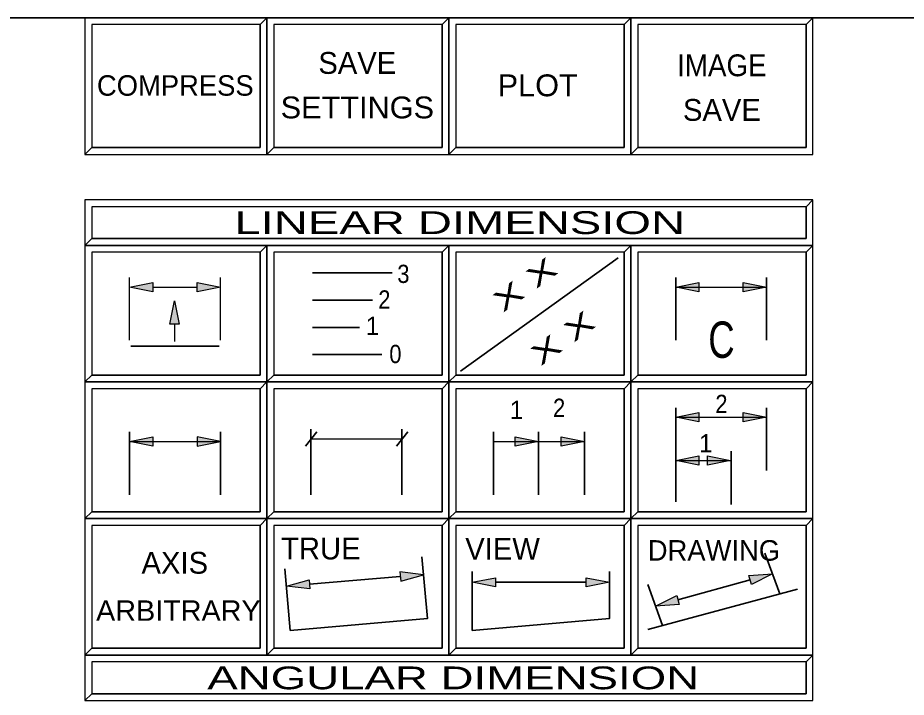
# Model space of a CAD drawing. Extents: x 95906.8 to 95923.6, y 90964.8 to 90972.8.
# Drawn here: x 95908.785 to 95910.737, y 90971.269 to 90972.762 of the extents above; entities that cross this region are included whole.
import ezdxf
from ezdxf.enums import TextEntityAlignment as Align

# ---------------------------------------------------------------- set-up
doc = ezdxf.new("R2010")
doc.units = 0
doc.header["$LTSCALE"] = 0.019
for name, color, linetype, lineweight in [('1', 7, 'Continuous', 25), ('11', 7, 'Continuous', 25), ('12', 7, 'Continuous', 25), ('17', 7, 'Continuous', 25), ('2', 7, 'Continuous', 13), ('3', 7, 'Continuous', 25), ('6', 7, 'Continuous', 35), ('7', 7, 'Continuous', 35)]:
    doc.layers.add(name, color=color, linetype=linetype, lineweight=lineweight)

msp = doc.modelspace()

# ---------------------------------------------------------------- hatches: boundary and pattern name
at = {"layer": '6'}
for points in [[(95909.0307, 90972.1701), (95909.0819, 90972.1803), (95909.0819, 90972.1599)], [(95909.1793, 90972.1803), (95909.2305, 90972.1701), (95909.1793, 90972.1599)], [(95910.2307, 90972.1701), (95910.2819, 90972.1803), (95910.2819, 90972.1599)], [(95910.3793, 90972.1803), (95910.4305, 90972.1701), (95910.3793, 90972.1599)], [(95909.1291, 90972.1397), (95909.1393, 90972.0885), (95909.1189, 90972.0885)], [(95910.2307, 90971.8841), (95910.2819, 90971.8943), (95910.2819, 90971.8739)], [(95910.3793, 90971.8943), (95910.4305, 90971.8841), (95910.3793, 90971.8739)], [(95909.0307, 90971.8308), (95909.0819, 90971.841), (95909.0819, 90971.8206)], [(95909.2305, 90971.8308), (95909.1793, 90971.841), (95909.1793, 90971.8206)], [(95909.8778, 90971.841), (95909.929, 90971.8308), (95909.8778, 90971.8206)], [(95909.9793, 90971.841), (95910.0305, 90971.8308), (95909.9793, 90971.8206)], [(95910.2307, 90971.7889), (95910.2819, 90971.7991), (95910.2819, 90971.7787)], [(95910.3003, 90971.7991), (95910.3515, 90971.7889), (95910.3003, 90971.7787)], [(95909.6767, 90971.5384), (95909.6248, 90971.5443), (95909.6265, 90971.5239)], [(95909.7835, 90971.5216), (95909.8347, 90971.5318), (95909.8347, 90971.5114)], [(95910.0339, 90971.5318), (95910.0851, 90971.5216), (95910.0339, 90971.5114)], [(95910.3915, 90971.5366), (95910.4436, 90971.5403), (95910.397, 90971.5168)], [(95909.3751, 90971.5129), (95909.4253, 90971.5274), (95909.427, 90971.507)], [(95910.1865, 90971.4695), (95910.2331, 90971.493), (95910.2386, 90971.4732)]]:
    msp.add_hatch(color=256, dxfattribs=at).paths.add_polyline_path(points)

# ---------------------------------------------------------------- linework, layer by layer
at = {"layer": '1'}
for points in [[(95908.9323, 90972.4617), (95909.3323, 90972.4617), (95909.3323, 90972.7617), (95908.9323, 90972.7617)], [(95909.3323, 90972.4617), (95909.7323, 90972.4617), (95909.7323, 90972.7617), (95909.3323, 90972.7617)], [(95909.7323, 90972.4617), (95910.1323, 90972.4617), (95910.1323, 90972.7617), (95909.7323, 90972.7617)], [(95910.1323, 90972.4617), (95910.5323, 90972.4617), (95910.5323, 90972.7617), (95910.1323, 90972.7617)], [(95908.9323, 90972.2617), (95910.5323, 90972.2617), (95910.5323, 90972.3617), (95908.9323, 90972.3617)], [(95908.9323, 90971.9617), (95909.3323, 90971.9617), (95909.3323, 90972.2617), (95908.9323, 90972.2617)], [(95909.3323, 90971.9617), (95909.7323, 90971.9617), (95909.7323, 90972.2617), (95909.3323, 90972.2617)], [(95909.7323, 90971.9617), (95910.1323, 90971.9617), (95910.1323, 90972.2617), (95909.7323, 90972.2617)], [(95910.1323, 90971.9617), (95910.5323, 90971.9617), (95910.5323, 90972.2617), (95910.1323, 90972.2617)], [(95908.9323, 90971.6617), (95909.3323, 90971.6617), (95909.3323, 90971.9617), (95908.9323, 90971.9617)], [(95909.3323, 90971.6617), (95909.7323, 90971.6617), (95909.7323, 90971.9617), (95909.3323, 90971.9617)], [(95909.7323, 90971.6617), (95910.1323, 90971.6617), (95910.1323, 90971.9617), (95909.7323, 90971.9617)], [(95910.1323, 90971.6617), (95910.5323, 90971.6617), (95910.5323, 90971.9617), (95910.1323, 90971.9617)], [(95908.9323, 90971.3617), (95909.3323, 90971.3617), (95909.3323, 90971.6617), (95908.9323, 90971.6617)], [(95909.3323, 90971.3617), (95909.7323, 90971.3617), (95909.7323, 90971.6617), (95909.3323, 90971.6617)], [(95909.7323, 90971.3617), (95910.1323, 90971.3617), (95910.1323, 90971.6617), (95909.7323, 90971.6617)], [(95910.1323, 90971.3617), (95910.5323, 90971.3617), (95910.5323, 90971.6617), (95910.1323, 90971.6617)], [(95908.9323, 90971.2617), (95910.5323, 90971.2617), (95910.5323, 90971.3617), (95908.9323, 90971.3617)]]:
    msp.add_lwpolyline(points, close=True, dxfattribs=at)
at = {"layer": '11'}
for points in [[(95908.9473, 90972.4767), (95909.3173, 90972.4767), (95909.3173, 90972.7467), (95908.9473, 90972.7467)], [(95909.3473, 90972.4767), (95909.7173, 90972.4767), (95909.7173, 90972.7467), (95909.3473, 90972.7467)], [(95909.7473, 90972.4767), (95910.1173, 90972.4767), (95910.1173, 90972.7467), (95909.7473, 90972.7467)], [(95908.9473, 90971.9767), (95909.3173, 90971.9767), (95909.3173, 90972.2467), (95908.9473, 90972.2467)], [(95909.3473, 90971.9767), (95909.7173, 90971.9767), (95909.7173, 90972.2467), (95909.3473, 90972.2467)], [(95909.7473, 90971.9767), (95910.1173, 90971.9767), (95910.1173, 90972.2467), (95909.7473, 90972.2467)], [(95910.1473, 90971.9767), (95910.5173, 90971.9767), (95910.5173, 90972.2467), (95910.1473, 90972.2467)], [(95909.3473, 90971.6767), (95909.7173, 90971.6767), (95909.7173, 90971.9467), (95909.3473, 90971.9467)], [(95909.7473, 90971.6767), (95910.1173, 90971.6767), (95910.1173, 90971.9467), (95909.7473, 90971.9467)], [(95910.1473, 90971.6767), (95910.5173, 90971.6767), (95910.5173, 90971.9467), (95910.1473, 90971.9467)], [(95908.9473, 90971.3767), (95909.3173, 90971.3767), (95909.3173, 90971.6467), (95908.9473, 90971.6467)], [(95909.3473, 90971.3767), (95909.7173, 90971.3767), (95909.7173, 90971.6467), (95909.3473, 90971.6467)], [(95909.7473, 90971.3767), (95910.1173, 90971.3767), (95910.1173, 90971.6467), (95909.7473, 90971.6467)], [(95910.1473, 90971.3767), (95910.5173, 90971.3767), (95910.5173, 90971.6467), (95910.1473, 90971.6467)]]:
    msp.add_lwpolyline(points, close=True, dxfattribs=at)
at = {"layer": '12'}
for points in [[(95910.1473, 90972.4767), (95910.5173, 90972.4767), (95910.5173, 90972.7467), (95910.1473, 90972.7467)], [(95908.9473, 90971.6767), (95909.3173, 90971.6767), (95909.3173, 90971.9467), (95908.9473, 90971.9467)]]:
    msp.add_lwpolyline(points, close=True, dxfattribs=at)
at = {"layer": '17'}
for points in [[(95908.9473, 90972.2767), (95910.5173, 90972.2767), (95910.5173, 90972.3467), (95908.9473, 90972.3467)], [(95908.9473, 90971.2767), (95910.5173, 90971.2767), (95910.5173, 90971.3467), (95908.9473, 90971.3467)]]:
    msp.add_lwpolyline(points, close=True, dxfattribs=at)
at = {"layer": '2'}
for points in [[(95908.9323, 90972.7617), (95908.9323, 90972.4617), (95908.9473, 90972.4767), (95908.9473, 90972.7467), (95909.3173, 90972.7467), (95909.3323, 90972.7617)], [(95909.3323, 90972.7617), (95909.3323, 90972.4617), (95909.3473, 90972.4767), (95909.3473, 90972.7467), (95909.7173, 90972.7467), (95909.7323, 90972.7617)], [(95909.7323, 90972.7617), (95909.7323, 90972.4617), (95909.7473, 90972.4767), (95909.7473, 90972.7467), (95910.1173, 90972.7467), (95910.1323, 90972.7617)], [(95910.1323, 90972.7617), (95910.1323, 90972.4617), (95910.1473, 90972.4767), (95910.1473, 90972.7467), (95910.5173, 90972.7467), (95910.5323, 90972.7617)], [(95908.9323, 90972.3617), (95908.9323, 90972.2617), (95908.9473, 90972.2767), (95908.9473, 90972.3467), (95910.5173, 90972.3467), (95910.5323, 90972.3617)], [(95908.9323, 90972.2617), (95908.9323, 90971.9617), (95908.9473, 90971.9767), (95908.9473, 90972.2467), (95909.3173, 90972.2467), (95909.3323, 90972.2617)], [(95909.3323, 90972.2617), (95909.3323, 90971.9617), (95909.3473, 90971.9767), (95909.3473, 90972.2467), (95909.7173, 90972.2467), (95909.7323, 90972.2617)], [(95909.7323, 90972.2617), (95909.7323, 90971.9617), (95909.7473, 90971.9767), (95909.7473, 90972.2467), (95910.1173, 90972.2467), (95910.1323, 90972.2617)], [(95910.1323, 90972.2617), (95910.1323, 90971.9617), (95910.1473, 90971.9767), (95910.1473, 90972.2467), (95910.5173, 90972.2467), (95910.5323, 90972.2617)], [(95908.9323, 90971.9617), (95908.9323, 90971.6617), (95908.9473, 90971.6767), (95908.9473, 90971.9467), (95909.3173, 90971.9467), (95909.3323, 90971.9617)], [(95909.3323, 90971.9617), (95909.3323, 90971.6617), (95909.3473, 90971.6767), (95909.3473, 90971.9467), (95909.7173, 90971.9467), (95909.7323, 90971.9617)], [(95909.7323, 90971.9617), (95909.7323, 90971.6617), (95909.7473, 90971.6767), (95909.7473, 90971.9467), (95910.1173, 90971.9467), (95910.1323, 90971.9617)], [(95910.1323, 90971.9617), (95910.1323, 90971.6617), (95910.1473, 90971.6767), (95910.1473, 90971.9467), (95910.5173, 90971.9467), (95910.5323, 90971.9617)], [(95908.9323, 90971.6617), (95908.9323, 90971.3617), (95908.9473, 90971.3767), (95908.9473, 90971.6467), (95909.3173, 90971.6467), (95909.3323, 90971.6617)], [(95909.3323, 90971.6617), (95909.3323, 90971.3617), (95909.3473, 90971.3767), (95909.3473, 90971.6467), (95909.7173, 90971.6467), (95909.7323, 90971.6617)], [(95909.7323, 90971.6617), (95909.7323, 90971.3617), (95909.7473, 90971.3767), (95909.7473, 90971.6467), (95910.1173, 90971.6467), (95910.1323, 90971.6617)], [(95910.1323, 90971.6617), (95910.1323, 90971.3617), (95910.1473, 90971.3767), (95910.1473, 90971.6467), (95910.5173, 90971.6467), (95910.5323, 90971.6617)], [(95908.9323, 90971.3617), (95908.9323, 90971.2617), (95908.9473, 90971.2767), (95908.9473, 90971.3467), (95910.5173, 90971.3467), (95910.5323, 90971.3617)]]:
    msp.add_lwpolyline(points, close=True, dxfattribs=at)
at = {"layer": '3'}
for points in [[(95908.9323, 90972.4617), (95909.3323, 90972.4617), (95909.3323, 90972.7617), (95909.3173, 90972.7467), (95909.3173, 90972.4767), (95908.9473, 90972.4767)], [(95909.3323, 90972.4617), (95909.7323, 90972.4617), (95909.7323, 90972.7617), (95909.7173, 90972.7467), (95909.7173, 90972.4767), (95909.3473, 90972.4767)], [(95909.7323, 90972.4617), (95910.1323, 90972.4617), (95910.1323, 90972.7617), (95910.1173, 90972.7467), (95910.1173, 90972.4767), (95909.7473, 90972.4767)], [(95910.1323, 90972.4617), (95910.5323, 90972.4617), (95910.5323, 90972.7617), (95910.5173, 90972.7467), (95910.5173, 90972.4767), (95910.1473, 90972.4767)], [(95908.9323, 90972.2617), (95910.5323, 90972.2617), (95910.5323, 90972.3617), (95910.5173, 90972.3467), (95910.5173, 90972.2767), (95908.9473, 90972.2767)], [(95908.9323, 90971.9617), (95909.3323, 90971.9617), (95909.3323, 90972.2617), (95909.3173, 90972.2467), (95909.3173, 90971.9767), (95908.9473, 90971.9767)], [(95909.3323, 90971.9617), (95909.7323, 90971.9617), (95909.7323, 90972.2617), (95909.7173, 90972.2467), (95909.7173, 90971.9767), (95909.3473, 90971.9767)], [(95909.7323, 90971.9617), (95910.1323, 90971.9617), (95910.1323, 90972.2617), (95910.1173, 90972.2467), (95910.1173, 90971.9767), (95909.7473, 90971.9767)], [(95910.1323, 90971.9617), (95910.5323, 90971.9617), (95910.5323, 90972.2617), (95910.5173, 90972.2467), (95910.5173, 90971.9767), (95910.1473, 90971.9767)], [(95908.9323, 90971.6617), (95909.3323, 90971.6617), (95909.3323, 90971.9617), (95909.3173, 90971.9467), (95909.3173, 90971.6767), (95908.9473, 90971.6767)], [(95909.3323, 90971.6617), (95909.7323, 90971.6617), (95909.7323, 90971.9617), (95909.7173, 90971.9467), (95909.7173, 90971.6767), (95909.3473, 90971.6767)], [(95909.7323, 90971.6617), (95910.1323, 90971.6617), (95910.1323, 90971.9617), (95910.1173, 90971.9467), (95910.1173, 90971.6767), (95909.7473, 90971.6767)], [(95910.1323, 90971.6617), (95910.5323, 90971.6617), (95910.5323, 90971.9617), (95910.5173, 90971.9467), (95910.5173, 90971.6767), (95910.1473, 90971.6767)], [(95908.9323, 90971.3617), (95909.3323, 90971.3617), (95909.3323, 90971.6617), (95909.3173, 90971.6467), (95909.3173, 90971.3767), (95908.9473, 90971.3767)], [(95909.3323, 90971.3617), (95909.7323, 90971.3617), (95909.7323, 90971.6617), (95909.7173, 90971.6467), (95909.7173, 90971.3767), (95909.3473, 90971.3767)], [(95909.7323, 90971.3617), (95910.1323, 90971.3617), (95910.1323, 90971.6617), (95910.1173, 90971.6467), (95910.1173, 90971.3767), (95909.7473, 90971.3767)], [(95910.1323, 90971.3617), (95910.5323, 90971.3617), (95910.5323, 90971.6617), (95910.5173, 90971.6467), (95910.5173, 90971.3767), (95910.1473, 90971.3767)], [(95908.9323, 90971.2617), (95910.5323, 90971.2617), (95910.5323, 90971.3617), (95910.5173, 90971.3467), (95910.5173, 90971.2767), (95908.9473, 90971.2767)]]:
    msp.add_lwpolyline(points, close=True, dxfattribs=at)
at = {"layer": '6'}
for p, q in [((95909.7575, 90971.9856), (95910.1045, 90972.2341)), ((95909.4323, 90972.2017), (95909.6076, 90972.2017)), ((95910.2307, 90972.0533), (95910.2307, 90972.1912)), ((95910.4305, 90972.0533), (95910.4305, 90972.1912)), ((95909.4323, 90972.1417), (95909.5646, 90972.1417)), ((95909.4323, 90972.0817), (95909.5356, 90972.0817)), ((95909.0334, 90972.0407), (95909.2276, 90972.0407)), ((95909.4323, 90972.0217), (95909.5847, 90972.0217)), ((95910.2307, 90971.6987), (95910.2307, 90971.9052)), ((95910.4305, 90971.7673), (95910.4305, 90971.9052)), ((95909.0307, 90971.714), (95909.0307, 90971.8519)), ((95909.2305, 90971.714), (95909.2305, 90971.8519)), ((95909.417, 90971.821), (95909.4423, 90971.8518)), ((95909.4289, 90971.714), (95909.4289, 90971.858)), ((95909.6169, 90971.821), (95909.6422, 90971.8518)), ((95909.6287, 90971.714), (95909.6287, 90971.858)), ((95909.8307, 90971.714), (95909.8307, 90971.8519)), ((95909.929, 90971.714), (95909.929, 90971.8519)), ((95910.0305, 90971.714), (95910.0305, 90971.8519)), ((95910.3526, 90971.6929), (95910.3526, 90971.81)), ((95910.4596, 90971.4961), (95910.427, 90971.5856)), ((95909.3835, 90971.4155), (95909.3716, 90971.5512)), ((95909.4261, 90971.5172), (95909.6256, 90971.5341)), ((95909.7835, 90971.4155), (95909.7835, 90971.5454)), ((95909.8347, 90971.5216), (95910.0339, 90971.5216)), ((95910.2019, 90971.427), (95910.1693, 90971.5165)), ((95910.2358, 90971.4831), (95910.3943, 90971.5267)), ((95910.1695, 90971.4183), (95910.4981, 90971.5064))]:
    msp.add_line(p, q, dxfattribs=at)
at = {"layer": '6', "lineweight": 25}
for p, q in [((95909.0307, 90972.0533), (95909.0307, 90972.1912)), ((95909.2305, 90972.0533), (95909.2305, 90972.1912)), ((95909.0819, 90972.1701), (95909.1793, 90972.1701)), ((95910.2307, 90972.1701), (95910.4305, 90972.1701)), ((95909.1291, 90972.0885), (95909.1291, 90972.0503)), ((95910.2307, 90971.8841), (95910.4305, 90971.8841)), ((95909.0307, 90971.8308), (95909.2305, 90971.8308)), ((95909.4289, 90971.8369), (95909.6287, 90971.8369)), ((95909.8307, 90971.8308), (95910.0305, 90971.8308)), ((95910.2307, 90971.7889), (95910.3515, 90971.7889))]:
    msp.add_line(p, q, dxfattribs=at)
for points in [[(95909.0307, 90972.1701), (95909.0819, 90972.1803), (95909.0819, 90972.1599)], [(95909.1793, 90972.1803), (95909.2305, 90972.1701), (95909.1793, 90972.1599)], [(95910.2307, 90972.1701), (95910.2819, 90972.1803), (95910.2819, 90972.1599)], [(95910.3793, 90972.1803), (95910.4305, 90972.1701), (95910.3793, 90972.1599)], [(95909.1291, 90972.1397), (95909.1393, 90972.0885), (95909.1189, 90972.0885)], [(95910.2307, 90971.8841), (95910.2819, 90971.8943), (95910.2819, 90971.8739)], [(95910.3793, 90971.8943), (95910.4305, 90971.8841), (95910.3793, 90971.8739)], [(95909.0307, 90971.8308), (95909.0819, 90971.841), (95909.0819, 90971.8206)], [(95909.2305, 90971.8308), (95909.1793, 90971.841), (95909.1793, 90971.8206)], [(95909.8778, 90971.841), (95909.929, 90971.8308), (95909.8778, 90971.8206)], [(95909.9793, 90971.841), (95910.0305, 90971.8308), (95909.9793, 90971.8206)], [(95910.2307, 90971.7889), (95910.2819, 90971.7991), (95910.2819, 90971.7787)], [(95910.3003, 90971.7991), (95910.3515, 90971.7889), (95910.3003, 90971.7787)], [(95909.6767, 90971.5384), (95909.6248, 90971.5443), (95909.6265, 90971.5239)], [(95909.7835, 90971.5216), (95909.8347, 90971.5318), (95909.8347, 90971.5114)], [(95910.0339, 90971.5318), (95910.0851, 90971.5216), (95910.0339, 90971.5114)], [(95910.3915, 90971.5366), (95910.4436, 90971.5403), (95910.397, 90971.5168)], [(95909.3751, 90971.5129), (95909.4253, 90971.5274), (95909.427, 90971.507)], [(95910.1865, 90971.4695), (95910.2331, 90971.493), (95910.2386, 90971.4732)]]:
    msp.add_lwpolyline(points, close=True, dxfattribs=at)
at = {"layer": '6'}
for points in [[(95909.3835, 90971.4155), (95909.6851, 90971.4419), (95909.6732, 90971.5776)], [(95909.7835, 90971.4155), (95910.0851, 90971.4419), (95910.0851, 90971.5454)]]:
    msp.add_lwpolyline(points, dxfattribs=at)
at = {"layer": '7'}
msp.add_lwpolyline([(95906.8323, 90972.7617), (95918.8323, 90972.7617), (95918.8323, 90964.7617), (95906.8323, 90964.7617)], close=True, dxfattribs=at)

# ---------------------------------------------------------------- texts
at = {"layer": '6'}
for s, height, p in [('SAVE', 0.048, (95909.531, 90972.6385)), ('COMPRESS', 0.045, (95909.131, 90972.5905)), ('SAVE', 0.048, (95910.3323, 90972.5353)), ('1', 0.04, (95909.5646, 90972.0652)), ('1', 0.04, (95909.881, 90971.8806)), ('1', 0.04, (95910.2969, 90971.8071)), ('TRUE', 0.048, (95909.4509, 90971.5719)), ('VIEW', 0.048, (95909.8503, 90971.5711)), ('DRAWING', 0.045, (95910.3148, 90971.5692)), ('AXIS', 0.048, (95909.1299, 90971.5405))]:
    msp.add_text(s, height=height, dxfattribs=at).set_placement(p, align=Align.CENTER)
for s, height, width, p in [('IMAGE', 0.048, 0.95, (95910.3322, 90972.6333)), ('PLOT', 0.048, 1.05, (95909.9275, 90972.5893)), ('SETTINGS', 0.048, 1.05, (95909.5311, 90972.5407)), ('3', 0.04, 0.9, (95909.6323, 90972.1792)), ('2', 0.04, 0.9, (95909.5905, 90972.1229)), ('0', 0.04, 0.9, (95909.6148, 90972.0032)), ('2', 0.04, 0.9, (95909.9746, 90971.885)), ('2', 0.04, 0.9, (95910.3313, 90971.8936)), ('ARBITRARY', 0.045, 1.05, (95909.1378, 90971.437))]:
    msp.add_text(s, height=height, dxfattribs=dict(at, width=width)).set_placement(p, align=Align.CENTER)
at = {"layer": '6', "width": 1.55}
for p in [(95909.949, 90972.1836), (95909.8764, 90972.1316), (95910.0318, 90972.0659), (95909.9592, 90972.0139)]:
    msp.add_text('X', height=0.045, rotation=35.608, dxfattribs=at).set_placement(p, align=Align.CENTER)
at = {"layer": '6', "width": 0.75}
msp.add_text('C', height=0.08, dxfattribs=at).set_placement((95910.3024, 90972.0146))
at = {"layer": '7'}
for s, width, p in [('    LINEAR DIMENSION   ', 1.55, (95909.7418, 90972.2867)), ('   ANGULAR DIMENSION   ', 1.5, (95909.7418, 90971.2867))]:
    msp.add_text(s, height=0.04999, dxfattribs=dict(at, width=width)).set_placement(p, align=Align.CENTER)

doc.saveas('drawing.dxf')
